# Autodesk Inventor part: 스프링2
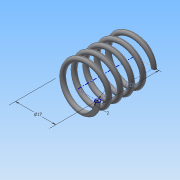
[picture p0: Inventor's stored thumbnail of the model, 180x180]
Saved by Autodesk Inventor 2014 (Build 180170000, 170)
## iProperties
Created: 2016-01
Part Number: 스프링2
Material: Generic
Document SubType Name: Modeling
Designer: Administrator
Density: 1 g/cm^3
Appearance: Default
Mass: 0.818602 g
Surface Area: 16.6857 cm^2
Volume: 0.818602 cm^3
Author: Administrator
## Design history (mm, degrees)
sketch "스케치1"
  geometry: L1 (0, 0)-(8.5, 0); L2 (8.5, 0)-(8.5, 17.5); L3 (8.5, 17.5)-(0, 17.5); L4 (0, 17.5)-(0, 0); C1 r 1 at (8.5, 0)
  constraints: 8 end point, 2 parallel, 1 centre point, 1 coincident, 1 horizontal, 1 perpendicular
  dimensions: "d0" = 17 diameter of L2 L4; "d1" = 17.5 distance of L1.end L2.end (derived); "d2" = 2 diameter of C1
feature "코일1" sketch "스케치1" pitch "d3" = 10; turns "d5" = 5; dims "d4" = 17.5 (= d1), "d6" = 0, angle "d7" = 90 deg, angle "d8" = 90 deg, "d9" = 0, "d10" = 0
node "작업 평면1"
sketch "스케치2"
  geometry: L1 (-9.5, 0)-(-7.5, 0) reference; 1 further point
  constraints: 1 horizontal alignment
extrude "돌출1" cut sketch "스케치2" distance "d12" = 10; taper "d13" = 0 deg
node "작업 평면2"
sketch "스케치3"
  geometry: L1 (-7.5, 0)-(-9.5, 0) reference; 1 further point
  constraints: 1 horizontal alignment
extrude "돌출2" cut sketch "스케치3" distance "d15" = 10; taper "d16" = 0 deg
node "솔리드1"
node "절단 모서리 투영1"
node "절단 모서리 투영2"
other parameters: "d11" = 0, "d14" = 17.5 (= d1)
